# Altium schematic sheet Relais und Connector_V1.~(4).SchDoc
size A4; SheetNumber: 6; SheetTotal: 7
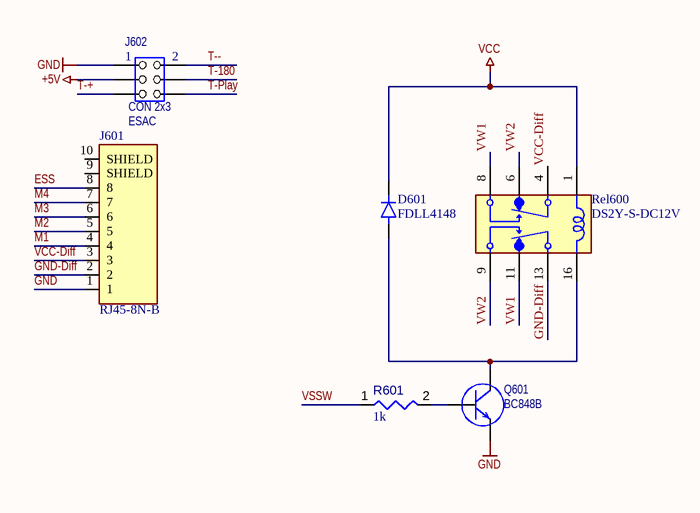
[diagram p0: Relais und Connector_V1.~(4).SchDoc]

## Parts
D601  FDLL4148  [DIOMELF3414N]
J601  RJ45-8N-B  [TE_RJ45-8N-B]
J602  CON 2x3  Use: ESAC  [J_2x3]
Q601  BC848B  [SOT-23]
R601  value 1k  [RESC1608X55X25ML10T15]  (hidden comment: Resistor 1k +/-1% 0603 100 mW)
Rel600  DS2Y-S-DC12V  [RELAY_DS2Y-S-DC12V]

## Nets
+5V: J602.3
GND: J601.1 J602.1 Q601.2(E)
VCC: D601.C Rel600.1(POS)
ESS: J601.8
GND-Diff: J601.2 Rel600.13(COM2)
M1: J601.4
M2: J601.5
M3: J601.6
M4: J601.7
T-180: J602.4
T-+: J602.5
T--: J602.2
T-Play: J602.6
VCC-Diff: J601.3 Rel600.4(COM1)
VSSW: R601.1
VW1: Rel600.8(NO1) Rel600.11(NC2)
VW2: Rel600.6(NC1) Rel600.9(NO2)
NetD601_A: D601.A Q601.3(C) Rel600.16(NEG)
NetQ601_1: Q601.1(B) R601.2

Not connected (* = marked no-connect by the designer): J601 9(SHIELD) 10(SHIELD)

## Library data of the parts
D601 = FDLL4148: Diode Standard 100 V 200mA Surface Mount SOD-80; MF: ON Semiconductor
J601 = RJ45-8N-B: RJ Jack / Signal Line EMI/RFI Filters 6 TERM LOW PROFILE BLOCK INDUCTOR 8 PIN
J602 = J_THT_IDC 2x3: Stecker
Q601 = Q_SMD_NPN: NPN Transistor
R601 = CMP-009-00014-5: Chip Resistor, 1 KOhm, +/-1%, 0.1 W, -55 to 155 degC, 0603 (1608 Metric); Voltage Rating: 50V; Power: 100mW; Tolerance: 1%
Rel600 = DS2Y-S-DC12V: General Purpose Relay DPDT _2 Form C_ Through Hole; MF: Panasonic Electric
